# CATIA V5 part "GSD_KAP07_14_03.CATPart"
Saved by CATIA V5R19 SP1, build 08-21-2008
Part number: GSD_KAP07_14_03
Definition: Beispielmodell für die Funktion Eckenverrundung / EdgeFillet - Ecken verrunden.
Description: CATIA V5 Flächenmodellierung  Copyright (c) 2009 Maik Hertha IT Consultants
Bounding box of the stored display mesh (mm): x -56.661 to 55.861, y -41.128 to 65.964, z -10 to 30
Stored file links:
  \GSD_BUCH_UEBUNG\GSD_KAP07_14_03.CATPart
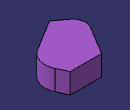
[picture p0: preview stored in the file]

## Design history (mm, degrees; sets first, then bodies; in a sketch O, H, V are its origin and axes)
AxisSystem1 "Absolute Axis System": origin (0, 0, 0), X (1, 0, 0), Y (0, 1, 0), Z (0, 0, 1)
Set1 "Edge Support"
  Plane1: type Equation, A 0, B 0, C 1, Length -10
  Point1: type OnPlane, Support Plane1, Direction (1, 0, 0), H 10, V 10
  Sketch1 on Plane1, origin (10, 10, -10), H (0, 1, 0), V (-1, 0, 0)
    line L1 (-51.1279, 33.3631) -> (-33.587, 56.515)
    arc A1 centre (-13.1715, 41.0472) radius 25.6134 from (-33.587, 56.515) to (0.0896, 62.9604) cw
    line L2 (0.0896, 62.9604) -> (55.9639, 29.1473)
    line L3 (55.9639, 29.1473) -> (55.9639, -32.6844)
    line L4 (55.9639, -32.6844) -> (35.6076, -42.197)
    arc A2 centre (19.1105, -6.8942) radius 38.9672 from (35.6076, -42.197) to (-11.5309, -30.968) cw
    line L5 (-11.5309, -30.968) -> (-51.1279, 33.3631)
    curve C1
    construction line L6 (-0.9087, -48.1015) -> (-25.9518, -8.5836)
    angle L5 L6 = 0.75
    tangency: A1 L1, L2 A1, A2 L4, L6 A2
    vertical: L3 V
  Split1: ToCut Plane1, Cutting Sketch1.C1
  Extrude1: Lim1 40, Lim2 0, Element1 Split1, Direction Plane1
Set2 "Edge 1"
  DatumSurface1: linked copy from another document
Body1 (main body)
